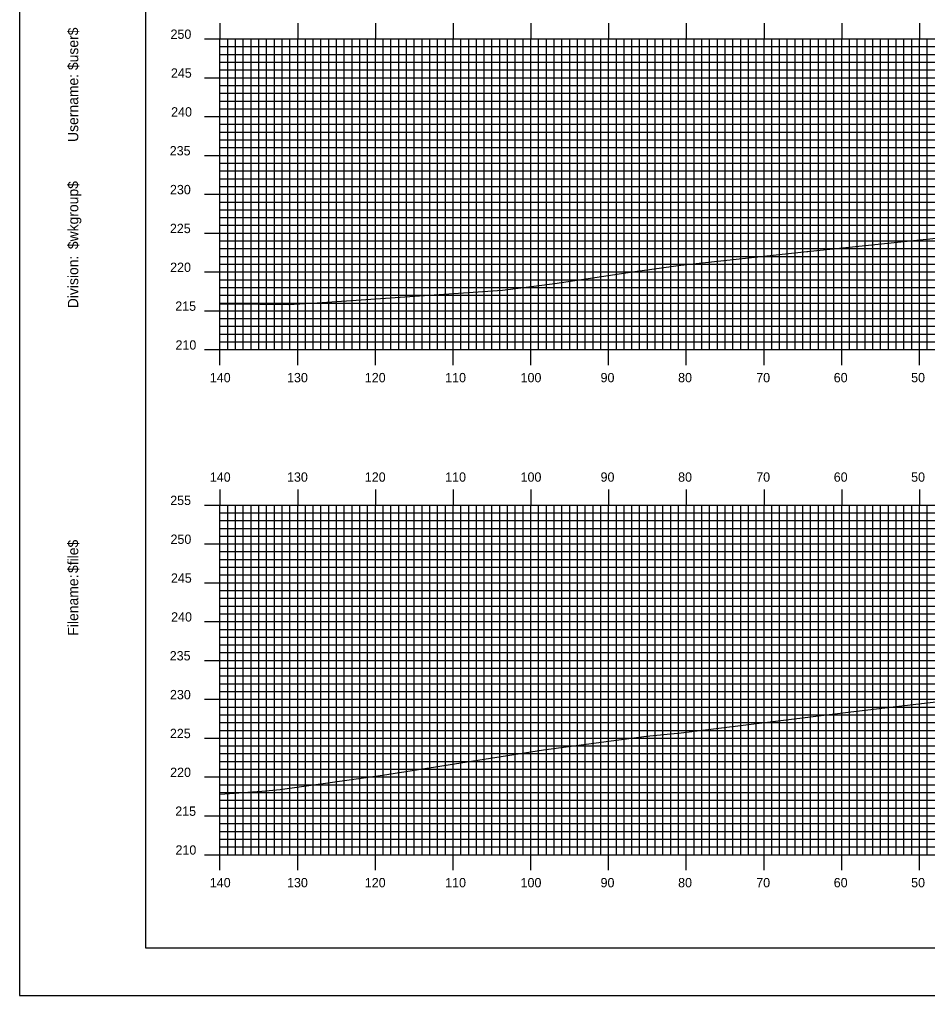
# Model space of a CAD drawing. Extents: x 1818457 to 1818800, y 442591 to 442811.
# Drawn here: x 1818456.9 to 1818573.7, y 442590.5 to 442716.2 of the extents above; entities that cross this region are included whole.
import ezdxf

# ---------------------------------------------------------------- set-up
doc = ezdxf.new("R2010")
doc.units = 0
for name, color, linetype in [('BORDER', 7, 'Continuous'), ('H_V ANNOTATION', 7, 'Continuous'), ('MAJOR', 7, 'Continuous'), ('MINOR', 7, 'Continuous'), ('PLOT BOUNDARY', 7, 'Continuous'), ('S_Roadway_Centerline', 7, 'Continuous')]:
    doc.layers.add(name, color=color, linetype=linetype)

msp = doc.modelspace()

# ---------------------------------------------------------------- linework, layer by layer
at = {"layer": 'BORDER'}
msp.add_lwpolyline([(1818473.04, 442596.67), (1818793.04, 442596.67), (1818793.04, 442806.67), (1818473.04, 442806.67)], close=True, dxfattribs=at)
at = {"layer": 'MAJOR'}
for p, q in [((1818482.64, 442715.67), (1818482.64, 442713.67)), ((1818492.64, 442715.67), (1818492.64, 442713.67)), ((1818502.64, 442715.67), (1818502.64, 442713.67)), ((1818512.64, 442715.67), (1818512.64, 442713.67)), ((1818522.64, 442715.67), (1818522.64, 442713.67)), ((1818532.64, 442715.67), (1818532.64, 442713.67)), ((1818542.64, 442715.67), (1818542.64, 442713.67)), ((1818552.64, 442715.67), (1818552.64, 442713.67)), ((1818562.64, 442715.67), (1818562.64, 442713.67)), ((1818572.64, 442715.67), (1818572.64, 442713.67)), ((1818480.63, 442713.67), (1818482.64, 442713.67)), ((1818482.64, 442713.67), (1818762.64, 442713.67)), ((1818482.64, 442673.67), (1818482.64, 442713.67)), ((1818482.64, 442673.67), (1818482.64, 442713.67)), ((1818482.64, 442713.67), (1818762.64, 442713.67)), ((1818492.64, 442673.67), (1818492.64, 442713.67)), ((1818502.64, 442673.67), (1818502.64, 442713.67)), ((1818512.64, 442673.67), (1818512.64, 442713.67)), ((1818522.64, 442673.67), (1818522.64, 442713.67)), ((1818532.64, 442673.67), (1818532.64, 442713.67)), ((1818542.64, 442673.67), (1818542.64, 442713.67)), ((1818552.64, 442673.67), (1818552.64, 442713.67)), ((1818562.64, 442673.67), (1818562.64, 442713.67)), ((1818572.64, 442673.67), (1818572.64, 442713.67)), ((1818480.63, 442708.67), (1818482.64, 442708.67)), ((1818482.64, 442708.67), (1818762.64, 442708.67)), ((1818480.63, 442703.67), (1818482.64, 442703.67)), ((1818482.64, 442703.67), (1818762.64, 442703.67)), ((1818480.63, 442698.67), (1818482.64, 442698.67)), ((1818482.64, 442698.67), (1818762.64, 442698.67)), ((1818480.63, 442693.67), (1818482.64, 442693.67)), ((1818482.64, 442693.67), (1818762.64, 442693.67)), ((1818480.63, 442688.67), (1818482.64, 442688.67)), ((1818482.64, 442688.67), (1818762.64, 442688.67)), ((1818480.63, 442683.67), (1818482.64, 442683.67)), ((1818482.64, 442683.67), (1818762.64, 442683.67)), ((1818480.63, 442678.67), (1818482.64, 442678.67)), ((1818482.64, 442678.67), (1818762.64, 442678.67)), ((1818480.63, 442673.67), (1818482.64, 442673.67)), ((1818482.64, 442673.67), (1818762.64, 442673.67)), ((1818482.64, 442673.67), (1818762.64, 442673.67)), ((1818482.64, 442671.66), (1818482.64, 442673.67)), ((1818492.64, 442671.66), (1818492.64, 442673.67)), ((1818502.64, 442671.66), (1818502.64, 442673.67)), ((1818512.64, 442671.66), (1818512.64, 442673.67)), ((1818522.64, 442671.66), (1818522.64, 442673.67)), ((1818532.64, 442671.66), (1818532.64, 442673.67)), ((1818542.64, 442671.66), (1818542.64, 442673.67)), ((1818552.64, 442671.66), (1818552.64, 442673.67)), ((1818562.64, 442671.66), (1818562.64, 442673.67)), ((1818572.64, 442671.66), (1818572.64, 442673.67)), ((1818482.64, 442655.67), (1818482.64, 442653.67)), ((1818492.64, 442655.67), (1818492.64, 442653.67)), ((1818502.64, 442655.67), (1818502.64, 442653.67)), ((1818512.64, 442655.67), (1818512.64, 442653.67)), ((1818522.64, 442655.67), (1818522.64, 442653.67)), ((1818532.64, 442655.67), (1818532.64, 442653.67)), ((1818542.64, 442655.67), (1818542.64, 442653.67)), ((1818552.64, 442655.67), (1818552.64, 442653.67)), ((1818562.64, 442655.67), (1818562.64, 442653.67)), ((1818572.64, 442655.67), (1818572.64, 442653.67)), ((1818480.63, 442653.67), (1818482.64, 442653.67)), ((1818482.64, 442653.67), (1818762.64, 442653.67)), ((1818482.64, 442608.67), (1818482.64, 442653.67)), ((1818482.64, 442608.67), (1818482.64, 442653.67)), ((1818482.64, 442653.67), (1818762.64, 442653.67)), ((1818492.64, 442608.67), (1818492.64, 442653.67)), ((1818502.64, 442608.67), (1818502.64, 442653.67)), ((1818512.64, 442608.67), (1818512.64, 442653.67)), ((1818522.64, 442608.67), (1818522.64, 442653.67)), ((1818532.64, 442608.67), (1818532.64, 442653.67)), ((1818542.64, 442608.67), (1818542.64, 442653.67)), ((1818552.64, 442608.67), (1818552.64, 442653.67)), ((1818562.64, 442608.67), (1818562.64, 442653.67)), ((1818572.64, 442608.67), (1818572.64, 442653.67)), ((1818480.63, 442648.67), (1818482.64, 442648.67)), ((1818482.64, 442648.67), (1818762.64, 442648.67)), ((1818480.63, 442643.67), (1818482.64, 442643.67)), ((1818482.64, 442643.67), (1818762.64, 442643.67)), ((1818480.63, 442638.67), (1818482.64, 442638.67)), ((1818482.64, 442638.67), (1818762.64, 442638.67)), ((1818480.63, 442633.67), (1818482.64, 442633.67)), ((1818482.64, 442633.67), (1818762.64, 442633.67)), ((1818480.63, 442628.67), (1818482.64, 442628.67)), ((1818482.64, 442628.67), (1818762.64, 442628.67)), ((1818480.63, 442623.67), (1818482.64, 442623.67)), ((1818482.64, 442623.67), (1818762.64, 442623.67)), ((1818480.63, 442618.67), (1818482.64, 442618.67)), ((1818482.64, 442618.67), (1818762.64, 442618.67)), ((1818480.63, 442613.67), (1818482.64, 442613.67)), ((1818482.64, 442613.67), (1818762.64, 442613.67)), ((1818480.63, 442608.67), (1818482.64, 442608.67)), ((1818482.64, 442608.67), (1818762.64, 442608.67)), ((1818482.64, 442608.67), (1818762.64, 442608.67)), ((1818482.64, 442606.66), (1818482.64, 442608.67)), ((1818492.64, 442606.66), (1818492.64, 442608.67)), ((1818502.64, 442606.66), (1818502.64, 442608.67)), ((1818512.64, 442606.66), (1818512.64, 442608.67)), ((1818522.64, 442606.66), (1818522.64, 442608.67)), ((1818532.64, 442606.66), (1818532.64, 442608.67)), ((1818542.64, 442606.66), (1818542.64, 442608.67)), ((1818552.64, 442606.66), (1818552.64, 442608.67)), ((1818562.64, 442606.66), (1818562.64, 442608.67)), ((1818572.64, 442606.66), (1818572.64, 442608.67))]:
    msp.add_line(p, q, dxfattribs=at)
at = {"layer": 'MINOR'}
for p, q in [((1818483.64, 442673.67), (1818483.64, 442713.67)), ((1818484.64, 442673.67), (1818484.64, 442713.67)), ((1818485.64, 442673.67), (1818485.64, 442713.67)), ((1818486.64, 442673.67), (1818486.64, 442713.67)), ((1818487.64, 442673.67), (1818487.64, 442713.67)), ((1818488.64, 442673.67), (1818488.64, 442713.67)), ((1818489.64, 442673.67), (1818489.64, 442713.67)), ((1818490.64, 442673.67), (1818490.64, 442713.67)), ((1818491.64, 442673.67), (1818491.64, 442713.67)), ((1818493.64, 442673.67), (1818493.64, 442713.67)), ((1818494.64, 442673.67), (1818494.64, 442713.67)), ((1818495.64, 442673.67), (1818495.64, 442713.67)), ((1818496.64, 442673.67), (1818496.64, 442713.67)), ((1818497.64, 442673.67), (1818497.64, 442713.67)), ((1818498.64, 442673.67), (1818498.64, 442713.67)), ((1818499.64, 442673.67), (1818499.64, 442713.67)), ((1818500.64, 442673.67), (1818500.64, 442713.67)), ((1818501.64, 442673.67), (1818501.64, 442713.67)), ((1818503.64, 442673.67), (1818503.64, 442713.67)), ((1818504.64, 442673.67), (1818504.64, 442713.67)), ((1818505.64, 442673.67), (1818505.64, 442713.67)), ((1818506.64, 442673.67), (1818506.64, 442713.67)), ((1818507.64, 442673.67), (1818507.64, 442713.67)), ((1818508.64, 442673.67), (1818508.64, 442713.67)), ((1818509.64, 442673.67), (1818509.64, 442713.67)), ((1818510.64, 442673.67), (1818510.64, 442713.67)), ((1818511.64, 442673.67), (1818511.64, 442713.67)), ((1818513.64, 442673.67), (1818513.64, 442713.67)), ((1818514.64, 442673.67), (1818514.64, 442713.67)), ((1818515.64, 442673.67), (1818515.64, 442713.67)), ((1818516.64, 442673.67), (1818516.64, 442713.67)), ((1818517.64, 442673.67), (1818517.64, 442713.67)), ((1818518.64, 442673.67), (1818518.64, 442713.67)), ((1818519.64, 442673.67), (1818519.64, 442713.67)), ((1818520.64, 442673.67), (1818520.64, 442713.67)), ((1818521.64, 442673.67), (1818521.64, 442713.67)), ((1818523.64, 442673.67), (1818523.64, 442713.67)), ((1818524.64, 442673.67), (1818524.64, 442713.67)), ((1818525.64, 442673.67), (1818525.64, 442713.67)), ((1818526.64, 442673.67), (1818526.64, 442713.67)), ((1818527.64, 442673.67), (1818527.64, 442713.67)), ((1818528.64, 442673.67), (1818528.64, 442713.67)), ((1818529.64, 442673.67), (1818529.64, 442713.67)), ((1818530.64, 442673.67), (1818530.64, 442713.67)), ((1818531.64, 442673.67), (1818531.64, 442713.67)), ((1818533.64, 442673.67), (1818533.64, 442713.67)), ((1818534.64, 442673.67), (1818534.64, 442713.67)), ((1818535.64, 442673.67), (1818535.64, 442713.67)), ((1818536.64, 442673.67), (1818536.64, 442713.67)), ((1818537.64, 442673.67), (1818537.64, 442713.67)), ((1818538.64, 442673.67), (1818538.64, 442713.67)), ((1818539.64, 442673.67), (1818539.64, 442713.67)), ((1818540.64, 442673.67), (1818540.64, 442713.67)), ((1818541.64, 442673.67), (1818541.64, 442713.67)), ((1818543.64, 442673.67), (1818543.64, 442713.67)), ((1818544.64, 442673.67), (1818544.64, 442713.67)), ((1818545.64, 442673.67), (1818545.64, 442713.67)), ((1818546.64, 442673.67), (1818546.64, 442713.67)), ((1818547.64, 442673.67), (1818547.64, 442713.67)), ((1818548.64, 442673.67), (1818548.64, 442713.67)), ((1818549.64, 442673.67), (1818549.64, 442713.67)), ((1818550.64, 442673.67), (1818550.64, 442713.67)), ((1818551.64, 442673.67), (1818551.64, 442713.67)), ((1818553.64, 442673.67), (1818553.64, 442713.67)), ((1818554.64, 442673.67), (1818554.64, 442713.67)), ((1818555.64, 442673.67), (1818555.64, 442713.67)), ((1818556.64, 442673.67), (1818556.64, 442713.67)), ((1818557.64, 442673.67), (1818557.64, 442713.67)), ((1818558.64, 442673.67), (1818558.64, 442713.67)), ((1818559.64, 442673.67), (1818559.64, 442713.67)), ((1818560.64, 442673.67), (1818560.64, 442713.67)), ((1818561.64, 442673.67), (1818561.64, 442713.67)), ((1818563.64, 442673.67), (1818563.64, 442713.67)), ((1818564.64, 442673.67), (1818564.64, 442713.67)), ((1818565.64, 442673.67), (1818565.64, 442713.67)), ((1818566.64, 442673.67), (1818566.64, 442713.67)), ((1818567.64, 442673.67), (1818567.64, 442713.67)), ((1818568.64, 442673.67), (1818568.64, 442713.67)), ((1818569.64, 442673.67), (1818569.64, 442713.67)), ((1818570.64, 442673.67), (1818570.64, 442713.67)), ((1818571.64, 442673.67), (1818571.64, 442713.67)), ((1818573.64, 442673.67), (1818573.64, 442713.67)), ((1818482.64, 442712.67), (1818762.64, 442712.67)), ((1818482.64, 442712.67), (1818484.64, 442712.67)), ((1818482.64, 442711.67), (1818762.64, 442711.67)), ((1818482.64, 442711.67), (1818484.64, 442711.67)), ((1818482.64, 442710.67), (1818762.64, 442710.67)), ((1818482.64, 442710.67), (1818484.64, 442710.67)), ((1818482.64, 442709.67), (1818762.64, 442709.67)), ((1818482.64, 442709.67), (1818484.64, 442709.67)), ((1818482.64, 442707.67), (1818762.64, 442707.67)), ((1818482.64, 442707.67), (1818484.64, 442707.67)), ((1818482.64, 442706.67), (1818762.64, 442706.67)), ((1818482.64, 442706.67), (1818484.64, 442706.67)), ((1818482.64, 442705.67), (1818762.64, 442705.67)), ((1818482.64, 442705.67), (1818484.64, 442705.67)), ((1818482.64, 442704.67), (1818762.64, 442704.67)), ((1818482.64, 442704.67), (1818484.64, 442704.67)), ((1818482.64, 442702.67), (1818762.64, 442702.67)), ((1818482.64, 442702.67), (1818484.64, 442702.67)), ((1818482.64, 442701.67), (1818762.64, 442701.67)), ((1818482.64, 442701.67), (1818484.64, 442701.67)), ((1818482.64, 442700.67), (1818762.64, 442700.67)), ((1818482.64, 442700.67), (1818484.64, 442700.67)), ((1818482.64, 442699.67), (1818762.64, 442699.67)), ((1818482.64, 442699.67), (1818484.64, 442699.67)), ((1818482.64, 442697.67), (1818762.64, 442697.67)), ((1818482.64, 442697.67), (1818484.64, 442697.67)), ((1818482.64, 442696.67), (1818762.64, 442696.67)), ((1818482.64, 442696.67), (1818484.64, 442696.67)), ((1818482.64, 442695.67), (1818762.64, 442695.67)), ((1818482.64, 442695.67), (1818484.64, 442695.67)), ((1818482.64, 442694.67), (1818762.64, 442694.67)), ((1818482.64, 442694.67), (1818484.64, 442694.67)), ((1818482.64, 442692.67), (1818762.64, 442692.67)), ((1818482.64, 442692.67), (1818484.64, 442692.67)), ((1818482.64, 442691.67), (1818762.64, 442691.67)), ((1818482.64, 442691.67), (1818484.64, 442691.67)), ((1818482.64, 442690.67), (1818762.64, 442690.67)), ((1818482.64, 442690.67), (1818484.64, 442690.67)), ((1818482.64, 442689.67), (1818762.64, 442689.67)), ((1818482.64, 442689.67), (1818484.64, 442689.67)), ((1818482.64, 442687.67), (1818762.64, 442687.67)), ((1818482.64, 442687.67), (1818484.64, 442687.67)), ((1818482.64, 442686.67), (1818762.64, 442686.67)), ((1818482.64, 442686.67), (1818484.64, 442686.67)), ((1818482.64, 442685.67), (1818762.64, 442685.67)), ((1818482.64, 442685.67), (1818484.64, 442685.67)), ((1818482.64, 442684.67), (1818762.64, 442684.67)), ((1818482.64, 442684.67), (1818484.64, 442684.67)), ((1818482.64, 442682.67), (1818762.64, 442682.67)), ((1818482.64, 442682.67), (1818484.64, 442682.67)), ((1818482.64, 442681.67), (1818762.64, 442681.67)), ((1818482.64, 442681.67), (1818484.64, 442681.67)), ((1818482.64, 442680.67), (1818762.64, 442680.67)), ((1818482.64, 442680.67), (1818484.64, 442680.67)), ((1818482.64, 442679.67), (1818762.64, 442679.67)), ((1818482.64, 442679.67), (1818484.64, 442679.67)), ((1818482.64, 442677.67), (1818762.64, 442677.67)), ((1818482.64, 442677.67), (1818484.64, 442677.67)), ((1818482.64, 442676.67), (1818762.64, 442676.67)), ((1818482.64, 442676.67), (1818484.64, 442676.67)), ((1818482.64, 442675.67), (1818762.64, 442675.67)), ((1818482.64, 442675.67), (1818484.64, 442675.67)), ((1818482.64, 442674.67), (1818762.64, 442674.67)), ((1818482.64, 442674.67), (1818484.64, 442674.67)), ((1818483.64, 442608.67), (1818483.64, 442653.67)), ((1818484.64, 442608.67), (1818484.64, 442653.67)), ((1818485.64, 442608.67), (1818485.64, 442653.67)), ((1818486.64, 442608.67), (1818486.64, 442653.67)), ((1818487.64, 442608.67), (1818487.64, 442653.67)), ((1818488.64, 442608.67), (1818488.64, 442653.67)), ((1818489.64, 442608.67), (1818489.64, 442653.67)), ((1818490.64, 442608.67), (1818490.64, 442653.67)), ((1818491.64, 442608.67), (1818491.64, 442653.67)), ((1818493.64, 442608.67), (1818493.64, 442653.67)), ((1818494.64, 442608.67), (1818494.64, 442653.67)), ((1818495.64, 442608.67), (1818495.64, 442653.67)), ((1818496.64, 442608.67), (1818496.64, 442653.67)), ((1818497.64, 442608.67), (1818497.64, 442653.67)), ((1818498.64, 442608.67), (1818498.64, 442653.67)), ((1818499.64, 442608.67), (1818499.64, 442653.67)), ((1818500.64, 442608.67), (1818500.64, 442653.67)), ((1818501.64, 442608.67), (1818501.64, 442653.67)), ((1818503.64, 442608.67), (1818503.64, 442653.67)), ((1818504.64, 442608.67), (1818504.64, 442653.67)), ((1818505.64, 442608.67), (1818505.64, 442653.67)), ((1818506.64, 442608.67), (1818506.64, 442653.67)), ((1818507.64, 442608.67), (1818507.64, 442653.67)), ((1818508.64, 442608.67), (1818508.64, 442653.67)), ((1818509.64, 442608.67), (1818509.64, 442653.67)), ((1818510.64, 442608.67), (1818510.64, 442653.67)), ((1818511.64, 442608.67), (1818511.64, 442653.67)), ((1818513.64, 442608.67), (1818513.64, 442653.67)), ((1818514.64, 442608.67), (1818514.64, 442653.67)), ((1818515.64, 442608.67), (1818515.64, 442653.67)), ((1818516.64, 442608.67), (1818516.64, 442653.67)), ((1818517.64, 442608.67), (1818517.64, 442653.67)), ((1818518.64, 442608.67), (1818518.64, 442653.67)), ((1818519.64, 442608.67), (1818519.64, 442653.67)), ((1818520.64, 442608.67), (1818520.64, 442653.67)), ((1818521.64, 442608.67), (1818521.64, 442653.67)), ((1818523.64, 442608.67), (1818523.64, 442653.67)), ((1818524.64, 442608.67), (1818524.64, 442653.67)), ((1818525.64, 442608.67), (1818525.64, 442653.67)), ((1818526.64, 442608.67), (1818526.64, 442653.67)), ((1818527.64, 442608.67), (1818527.64, 442653.67)), ((1818528.64, 442608.67), (1818528.64, 442653.67)), ((1818529.64, 442608.67), (1818529.64, 442653.67)), ((1818530.64, 442608.67), (1818530.64, 442653.67)), ((1818531.64, 442608.67), (1818531.64, 442653.67)), ((1818533.64, 442608.67), (1818533.64, 442653.67)), ((1818534.64, 442608.67), (1818534.64, 442653.67)), ((1818535.64, 442608.67), (1818535.64, 442653.67)), ((1818536.64, 442608.67), (1818536.64, 442653.67)), ((1818537.64, 442608.67), (1818537.64, 442653.67)), ((1818538.64, 442608.67), (1818538.64, 442653.67)), ((1818539.64, 442608.67), (1818539.64, 442653.67)), ((1818540.64, 442608.67), (1818540.64, 442653.67)), ((1818541.64, 442608.67), (1818541.64, 442653.67)), ((1818543.64, 442608.67), (1818543.64, 442653.67)), ((1818544.64, 442608.67), (1818544.64, 442653.67)), ((1818545.64, 442608.67), (1818545.64, 442653.67)), ((1818546.64, 442608.67), (1818546.64, 442653.67)), ((1818547.64, 442608.67), (1818547.64, 442653.67)), ((1818548.64, 442608.67), (1818548.64, 442653.67)), ((1818549.64, 442608.67), (1818549.64, 442653.67)), ((1818550.64, 442608.67), (1818550.64, 442653.67)), ((1818551.64, 442608.67), (1818551.64, 442653.67)), ((1818553.64, 442608.67), (1818553.64, 442653.67)), ((1818554.64, 442608.67), (1818554.64, 442653.67)), ((1818555.64, 442608.67), (1818555.64, 442653.67)), ((1818556.64, 442608.67), (1818556.64, 442653.67)), ((1818557.64, 442608.67), (1818557.64, 442653.67)), ((1818558.64, 442608.67), (1818558.64, 442653.67)), ((1818559.64, 442608.67), (1818559.64, 442653.67)), ((1818560.64, 442608.67), (1818560.64, 442653.67)), ((1818561.64, 442608.67), (1818561.64, 442653.67)), ((1818563.64, 442608.67), (1818563.64, 442653.67)), ((1818564.64, 442608.67), (1818564.64, 442653.67)), ((1818565.64, 442608.67), (1818565.64, 442653.67)), ((1818566.64, 442608.67), (1818566.64, 442653.67)), ((1818567.64, 442608.67), (1818567.64, 442653.67)), ((1818568.64, 442608.67), (1818568.64, 442653.67)), ((1818569.64, 442608.67), (1818569.64, 442653.67)), ((1818570.64, 442608.67), (1818570.64, 442653.67)), ((1818571.64, 442608.67), (1818571.64, 442653.67)), ((1818573.64, 442608.67), (1818573.64, 442653.67)), ((1818482.64, 442652.67), (1818762.64, 442652.67)), ((1818482.64, 442652.67), (1818484.64, 442652.67)), ((1818482.64, 442651.67), (1818762.64, 442651.67)), ((1818482.64, 442651.67), (1818484.64, 442651.67)), ((1818482.64, 442650.67), (1818762.64, 442650.67)), ((1818482.64, 442650.67), (1818484.64, 442650.67)), ((1818482.64, 442649.67), (1818762.64, 442649.67)), ((1818482.64, 442649.67), (1818484.64, 442649.67)), ((1818482.64, 442647.67), (1818762.64, 442647.67)), ((1818482.64, 442647.67), (1818484.64, 442647.67)), ((1818482.64, 442646.67), (1818762.64, 442646.67)), ((1818482.64, 442646.67), (1818484.64, 442646.67)), ((1818482.64, 442645.67), (1818762.64, 442645.67)), ((1818482.64, 442645.67), (1818484.64, 442645.67)), ((1818482.64, 442644.67), (1818762.64, 442644.67)), ((1818482.64, 442644.67), (1818484.64, 442644.67)), ((1818482.64, 442642.67), (1818762.64, 442642.67)), ((1818482.64, 442642.67), (1818484.64, 442642.67)), ((1818482.64, 442641.67), (1818762.64, 442641.67)), ((1818482.64, 442641.67), (1818484.64, 442641.67)), ((1818482.64, 442640.67), (1818762.64, 442640.67)), ((1818482.64, 442640.67), (1818484.64, 442640.67)), ((1818482.64, 442639.67), (1818762.64, 442639.67)), ((1818482.64, 442639.67), (1818484.64, 442639.67)), ((1818482.64, 442637.67), (1818762.64, 442637.67)), ((1818482.64, 442637.67), (1818484.64, 442637.67)), ((1818482.64, 442636.67), (1818762.64, 442636.67)), ((1818482.64, 442636.67), (1818484.64, 442636.67)), ((1818482.64, 442635.67), (1818762.64, 442635.67)), ((1818482.64, 442635.67), (1818484.64, 442635.67)), ((1818482.64, 442634.67), (1818762.64, 442634.67)), ((1818482.64, 442634.67), (1818484.64, 442634.67)), ((1818482.64, 442632.67), (1818762.64, 442632.67)), ((1818482.64, 442632.67), (1818484.64, 442632.67)), ((1818482.64, 442631.67), (1818762.64, 442631.67)), ((1818482.64, 442631.67), (1818484.64, 442631.67)), ((1818482.64, 442630.67), (1818762.64, 442630.67)), ((1818482.64, 442630.67), (1818484.64, 442630.67)), ((1818482.64, 442629.67), (1818762.64, 442629.67)), ((1818482.64, 442629.67), (1818484.64, 442629.67)), ((1818482.64, 442627.67), (1818762.64, 442627.67)), ((1818482.64, 442627.67), (1818484.64, 442627.67)), ((1818482.64, 442626.67), (1818762.64, 442626.67)), ((1818482.64, 442626.67), (1818484.64, 442626.67)), ((1818482.64, 442625.67), (1818762.64, 442625.67)), ((1818482.64, 442625.67), (1818484.64, 442625.67)), ((1818482.64, 442624.67), (1818762.64, 442624.67)), ((1818482.64, 442624.67), (1818484.64, 442624.67)), ((1818482.64, 442622.67), (1818762.64, 442622.67)), ((1818482.64, 442622.67), (1818484.64, 442622.67)), ((1818482.64, 442621.67), (1818762.64, 442621.67)), ((1818482.64, 442621.67), (1818484.64, 442621.67)), ((1818482.64, 442620.67), (1818762.64, 442620.67)), ((1818482.64, 442620.67), (1818484.64, 442620.67)), ((1818482.64, 442619.67), (1818762.64, 442619.67)), ((1818482.64, 442619.67), (1818484.64, 442619.67)), ((1818482.64, 442617.67), (1818762.64, 442617.67)), ((1818482.64, 442617.67), (1818484.64, 442617.67)), ((1818482.64, 442616.67), (1818762.64, 442616.67)), ((1818482.64, 442616.67), (1818484.64, 442616.67)), ((1818482.64, 442615.67), (1818762.64, 442615.67)), ((1818482.64, 442615.67), (1818484.64, 442615.67)), ((1818482.64, 442614.67), (1818762.64, 442614.67)), ((1818482.64, 442614.67), (1818484.64, 442614.67)), ((1818482.64, 442612.67), (1818762.64, 442612.67)), ((1818482.64, 442612.67), (1818484.64, 442612.67)), ((1818482.64, 442611.67), (1818762.64, 442611.67)), ((1818482.64, 442611.67), (1818484.64, 442611.67)), ((1818482.64, 442610.67), (1818762.64, 442610.67)), ((1818482.64, 442610.67), (1818484.64, 442610.67)), ((1818482.64, 442609.67), (1818762.64, 442609.67)), ((1818482.64, 442609.67), (1818484.64, 442609.67))]:
    msp.add_line(p, q, dxfattribs=at)
at = {"layer": 'PLOT BOUNDARY'}
msp.add_lwpolyline([(1818456.85, 442590.55), (1818796.85, 442590.55), (1818796.85, 442810.55), (1818456.85, 442810.55)], close=True, dxfattribs=at)
at = {"layer": 'S_Roadway_Centerline'}
for points in [[(1818482.64, 442679.51), (1818484.04, 442679.57), (1818491.45, 442679.48), (1818495.16, 442679.68), (1818518.99, 442681.32), (1818525.73, 442682.17), (1818536.04, 442683.71), (1818541.95, 442684.53), (1818557.76, 442686.24), (1818558.13, 442686.29), (1818558.26, 442686.3), (1818558.62, 442686.34), (1818592.64, 442689.86)], [(1818482.64, 442616.45), (1818483.28, 442616.5), (1818488.02, 442616.83), (1818490.39, 442617.04), (1818503.57, 442618.9), (1818524.25, 442622.15), (1818537.51, 442623.92), (1818541.99, 442624.35), (1818563.45, 442627), (1818572.16, 442628.02), (1818582.15, 442629.22)]]:
    msp.add_lwpolyline(points, dxfattribs=at)

# ---------------------------------------------------------------- texts
at = {"layer": 'BORDER'}
for s, p in [('$user$', (1818464.41, 442709.65)), ('Username:', (1818464.41, 442700.4)), ('$wkgroup$', (1818464.41, 442686.6)), ('Division:', (1818464.41, 442679)), ('$file$', (1818464.41, 442644.92)), ('Filename:', (1818464.41, 442636.86))]:
    msp.add_text(s, height=1.339, rotation=90, dxfattribs=at).set_placement(p)
at = {"layer": 'H_V ANNOTATION'}
for s, p in [('250', (1818476.28, 442713.67)), ('245', (1818476.33, 442708.67)), ('240', (1818476.36, 442703.67)), ('235', (1818476.18, 442698.67)), ('230', (1818476.21, 442693.67)), ('225', (1818476.2, 442688.67)), ('220', (1818476.23, 442683.67)), ('215', (1818476.89, 442678.67)), ('210', (1818476.92, 442673.67)), ('140', (1818481.34, 442669.47)), ('130', (1818491.27, 442669.47)), ('120', (1818501.28, 442669.47)), ('110', (1818511.62, 442669.47)), ('100', (1818521.32, 442669.47)), ('90', (1818531.61, 442669.47)), ('80', (1818541.59, 442669.47)), ('70', (1818551.64, 442669.47)), ('60', (1818561.61, 442669.47)), ('50', (1818571.57, 442669.47)), ('140', (1818481.34, 442656.67)), ('130', (1818491.27, 442656.67)), ('120', (1818501.28, 442656.67)), ('110', (1818511.62, 442656.67)), ('100', (1818521.32, 442656.67)), ('90', (1818531.61, 442656.67)), ('80', (1818541.59, 442656.67)), ('70', (1818551.64, 442656.67)), ('60', (1818561.61, 442656.67)), ('50', (1818571.57, 442656.67)), ('255', (1818476.24, 442653.67)), ('250', (1818476.28, 442648.67)), ('245', (1818476.33, 442643.67)), ('240', (1818476.36, 442638.67)), ('235', (1818476.18, 442633.67)), ('230', (1818476.21, 442628.67)), ('225', (1818476.2, 442623.67)), ('220', (1818476.23, 442618.67)), ('215', (1818476.89, 442613.67)), ('210', (1818476.92, 442608.67)), ('140', (1818481.34, 442604.47)), ('130', (1818491.27, 442604.47)), ('120', (1818501.28, 442604.47)), ('110', (1818511.62, 442604.47)), ('100', (1818521.32, 442604.47)), ('90', (1818531.61, 442604.47)), ('80', (1818541.59, 442604.47)), ('70', (1818551.64, 442604.47)), ('60', (1818561.61, 442604.47)), ('50', (1818571.57, 442604.47))]:
    msp.add_text(s, height=1.2, dxfattribs=at).set_placement(p)
at = {"layer": 'MAJOR'}
for p in [(1818482.63, 442673.67), (1818482.63, 442608.67)]:
    msp.add_text('-', height=0.012, dxfattribs=at).set_placement(p)

doc.saveas('drawing.dxf')
